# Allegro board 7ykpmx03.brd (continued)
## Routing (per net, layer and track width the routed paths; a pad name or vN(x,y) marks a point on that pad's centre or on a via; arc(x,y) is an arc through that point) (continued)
SMB_RST_N: length 68.9
  TOP w0.102: P_OCP.A9 90.06,91.8 89.53,92.33 v1(89.53,92.84)
  BOTTOM w0.102: v1(89.53,92.84) 89.53,91.57 89.84,91.26 89.84,89.61 89.41,89.18 89.41,87.63 88.87,87.1 83.44,87.1 78.05,81.71 66.12,81.71 62.99,84.84 50.16,84.84 47.24,81.91 39.78,81.91 36.88,84.81 36.88,85.37 35.76,86.49 TP21.TEST
SMB_SDA: length 64.8
  TOP w0.102: v1(89.41,89.92) 89.46,89.97 P_OCP.A8
  BOTTOM w0.102: v1(89.41,89.92) 88.39,90.93 82.8,90.93 81.98,90.11 81.98,87.34 80.85,86.21 80.85,85.14 77.93,82.22 66.5,82.22 63.25,85.47 50.04,85.47 46.93,82.36 39.96,82.36 38.07,84.25 38.07,85.5 TP20.TEST
V_1P65: length 1.1
  TOP w0.254: R35.2 112.81,250.96 ; R35.2 112.16,250.96 ; R35.2 112.48,250.63
  TOP w0.381: v1(117.31,254.38) 117.22,254.38
  vias: v1(118.2,254.38) v1(119.09,254.38) v1(119.98,254.38)
V_1P65_NEG: length 82.3
  TOP w0.254: R45.2 104.99,260.41
  TOP w0.508: 104.99,260.41 104.99,261.33 106.55,262.89 123.83,262.89 127,259.71 127,240.03 133.35,233.68 156.84,233.68 158.75,235.59 v1(159.51,235.59) ; R99.2 165.28,238.84 v1(164.85,239.27)
  vias: v1(164.47,241.68) v1(165.23,241.68)
V_3P3: length 126
  TOP w0.203: U19.5 67.42,221.87 67.67,222.12 v1(67.82,222.12) ; U8.9 C16.1
  TOP w0.254: U17.1 61.91,243.14 62.1,242.95 62.1,242.32 C130.1 v1(61.51,242.32) ; U5.5 29.96,239.66 C9.2 29.98,239.26 v1(30.23,239.01) ; U14.5 31.69,250.26 31.62,250.19 C59.2 31.24,249.81 v1(30.99,249.56) ; v1(24.26,222.38) R26.1 ; C147.1 64.77,223.14 v1(65.02,222.89) ; L10.1 v1(74.04,221.74) ; R191.2 v1(56.88,235.59) ; R36.2 v1(110.45,250.32) ; v1(30.23,234.19) 29.98,234.44 C13.2 29.96,234.84 U7.5 ; R43.2 v1(59.14,241.17) ; C16.1 105.02,240.01 v1(104.79,239.78) ; v1(30.23,231.01) 29.98,231.26 C7.2 29.96,231.66 U4.5 ; U2.5 29.96,228.49 C8.2 29.98,228.09 v1(30.23,227.84) ; U16.5 40.96,250.51 40.89,250.44 C129.2 40.51,250.06 v1(40.26,249.81) ; v1(13.73,217.68) 13.97,217.91 C5.1 14.48,218.31 ; R186.2 v1(61.48,239.52) ; v1(22.99,231.65) 23.24,231.4 C12.2 23.64,231.01 23.94,230.72 U6.5 ; R192.2 v1(50.94,235.59) ; U1.5 23.94,237.07 23.64,237.36 C6.2 23.24,237.75 v1(22.99,238) ; R187.2 v1(54.61,236.99) ; R211.2 v1(60.06,218.69) ; L7.1 63.88,222.5 v1(63.75,222.63) ; U21.5 53.48,248.14 C153.2 v1(54.06,248.16) ; R206.2 v1(72.56,225.09) ; 64.64,229.29 v1(63.94,229.29) ; R205.2 v1(69.63,229.29) ; R207.2 v1(68.26,225.09) ; R44.2 v1(59.14,241.94) ; U20.14 78.27,211.5 C152.1 v1(78.28,210.92) ; R38.2 v1(108.46,250.16) ; L8.1 v1(64.01,214.17) ; R203.2 v1(55.24,246.88) ; R17.1 v1(145.8,89.92) ; R39.2 v1(105.44,250.16) ; C131.1 v1(61.33,241.05)
  TOP w0.381: v1(36.07,87.5) 35.64,87.93 R13.1 ; R28.2 v1(20.68,239.78) ; U3.8 14.48,218.31 ; R5.1 33.6,87.93 v1(34.04,87.5) ; R1.2 v1(115.7,95.25) ; P_OCP.B11 v1(91.26,84.71) ; R20.2 v1(24.61,226.7) ; R30.2 v1(27.05,220.98) ; v1(38.1,87.5) 37.67,87.93 R12.1
  TOP w0.508: R185.2 v1(48.01,251.46) ; U11.4 24.19,245.8 v1(23.49,245.11) ; U12.4 28.76,252.04 v1(28.83,251.97) ; R10.2 v1(141.35,89.92) ; R86.2 v1(86.73,220.79) ; U13.4 v1(31.24,246.31) ; R95.1 v1(167.64,230.51) ; R9.2 v1(34.92,97.03) ; R89.2 v1(95.62,220.79) ; R88.2 v1(86.73,208.73) ; R97.1 v1(152.4,230.51) ; R87.2 v1(95.62,208.73) ; v1(40.51,246.56) U15.4
  VCC w0.254: SW_OE2.6 82.14,205.95 ; SW_OE2.6 82.14,204.78 ; SW_OE2.6 80.96,205.95 ; SW_OE2.6 80.96,204.78 ; 89.85,209.95 SW_OE1.4 ; SW_OE1.4 89.85,208.78 ; SW_OE1.4 91.03,209.95 ; SW_OE1.4 91.03,208.78 ; P_ATX.12 194.09,256.92 ; P_ATX.12 194.09,255.31 ; P_ATX.12 192.47,255.31 ; P_ATX.12 192.47,256.92 ; 80.96,208.78 SW_OE2.4 ; SW_OE2.4 82.14,209.95 ; SW_OE2.4 80.96,209.95 ; SW_OE2.4 82.14,208.78 ; 89.85,221.48 SW_OE3.4 ; SW_OE3.4 91.03,222.65 ; SW_OE3.4 91.03,221.48 ; SW_OE3.4 89.85,222.65 ; SW_OE3.6 91.03,218.65 ; SW_OE3.6 89.85,217.48 ; SW_OE3.6 91.03,217.48 ; SW_OE3.6 89.85,218.65 ; P_ATX.2 152.08,256.92 ; P_ATX.2 150.47,255.31 ; P_ATX.2 152.08,255.31 ; P_ATX.2 150.47,256.92 ; SW_OE0.6 82.14,217.48 ; SW_OE0.6 80.96,218.65 ; SW_OE0.6 82.14,218.65 ; SW_OE0.6 80.96,217.48 ; SW_OE1.6 91.03,204.78 ; SW_OE1.6 91.03,205.95 ; SW_OE1.6 89.85,204.78 ; SW_OE1.6 89.85,205.95 ; 71.37,231.73 P7.1 69.9,231.73 ; 146.27,256.92 P_ATX.1 ; P_ATX.1 147.89,256.92 ; P_ATX.1 146.27,255.31 ; P_ATX.1 147.89,255.31 ; 146.27,251.42 P_ATX.13 ; P_ATX.13 147.89,251.42 ; P_ATX.13 147.89,249.81 ; P_ATX.13 146.27,249.81 ; P6.1 58.39,231.68 ; P6.1 58.39,233.14 ; P6.1 56.92,231.68 ; P6.1 56.92,233.14 ; 47.57,224.99 SW2.1 ; SW2.1 48.95,224.99 ; SW2.1 47.57,226.36 ; SW2.1 48.95,226.36 ; 80.96,221.48 SW_OE0.4 ; SW_OE0.4 82.14,222.65 ; SW_OE0.4 80.96,222.65 ; SW_OE0.4 82.14,221.48
  BOTTOM w0.254: L9.1 68.65,214.43 v1(68.71,214.38) ; C146.1 67.44,221.74 v1(67.82,222.12)
  BOTTOM w0.406: v1(112.52,94.49) 112.47,94.54 R3.2
  vias: v1(12.07,220.47) v1(12.07,219.33) v1(17.02,175.39) v1(17.02,173.61) v1(17.02,172.09) v1(17.02,170.43) v1(17.53,200.15) v1(17.53,198.37) v1(17.53,196.85) v1(17.53,195.2) v1(17.78,110.36) v1(17.78,108.58) v1(17.78,107.06) v1(17.78,105.41) v1(17.91,144.15) v1(17.91,142.37) v1(17.91,140.84) v1(17.91,139.19) v1(21.08,87.88) v1(21.08,86.11) v1(21.08,84.58) v1(21.08,82.93) v1(22.86,87.88) v1(22.86,86.11) v1(22.86,84.58) v1(22.86,82.93) v1(24.64,87.88) v1(24.64,86.11) v1(24.64,84.58) v1(24.64,82.93) v1(25.4,209.3) v1(25.4,207.77) v1(25.4,206.12) v1(27.43,209.3) v1(27.43,207.77) v1(27.43,206.12) v1(29.34,209.3) v1(29.34,207.77) v1(29.34,206.12) v1(31.37,209.3) v1(31.37,207.77) v1(31.37,206.25) v1(32.26,236.6) v1(32.26,235.71) v1(32.26,231.01) v1(32.26,230.12) v1(33.15,234.7) v1(33.15,233.81) v1(33.15,232.92) v1(33.15,232.03) v1(87.12,83.69) v1(87.88,83.69) v1(91.19,83.82) v1(91.82,84.2) v1(137.03,254.38) v1(137.03,253.49) v1(137.03,252.6) v1(137.03,251.71) v1(137.92,256.29) v1(137.92,255.4) v1(137.92,250.7) v1(137.92,249.81)
V_5V: length 58.1
  TOP w0.254: P_ATX.4 160.48,255.31 ; P_ATX.4 158.87,256.92 ; P_ATX.4 160.48,256.92 ; P_ATX.4 158.87,255.31 ; P_ATX.6 168.89,256.92 ; P_ATX.6 167.27,256.92 ; P_ATX.6 168.89,255.31 ; P_ATX.6 167.27,255.31 ; 179.87,249.81 P_ATX.21 ; P_ATX.21 179.87,251.42 ; P_ATX.21 181.48,251.42 ; P_ATX.21 181.48,249.81 ; 188.27,249.81 P_ATX.23 ; P_ATX.23 188.27,251.42 ; P_ATX.23 189.88,251.42 ; P_ATX.23 189.88,249.81 ; 184.07,251.42 P_ATX.22 ; P_ATX.22 185.69,251.42 ; P_ATX.22 185.69,249.81 ; P_ATX.22 184.07,249.81
  TOP w0.508: 120.36,256.83 C36.2 120.79,258.88 v1(121.5,259.59)
  VCC w0.254: P_ATX.21 181.48,251.42 ; P_ATX.21 181.48,249.81 ; P_ATX.21 179.87,249.81 ; P_ATX.21 179.87,251.42 ; P_ATX.4 160.48,256.92 ; P_ATX.4 158.87,255.31 ; P_ATX.4 160.48,255.31 ; P_ATX.4 158.87,256.92 ; P_ATX.6 168.89,256.92 ; P_ATX.6 167.27,256.92 ; P_ATX.6 168.89,255.31 ; P_ATX.6 167.27,255.31 ; P_ATX.22 185.69,249.81 ; P_ATX.22 184.07,251.42 ; P_ATX.22 185.69,251.42 ; P_ATX.22 184.07,249.81 ; 188.27,249.81 P_ATX.23 ; P_ATX.23 189.88,249.81 ; P_ATX.23 189.88,251.42 ; P_ATX.23 188.27,251.42
  BOTTOM w0.254: P_ATX.4 160.48,255.31 ; P_ATX.4 158.87,255.31 ; P_ATX.4 160.48,256.92 ; P_ATX.4 158.87,256.92 ; 167.27,255.31 P_ATX.6 ; P_ATX.6 168.89,256.92 ; P_ATX.6 168.89,255.31 ; P_ATX.6 167.27,256.92
V_5VSTBY: length 37.2
  TOP w0.508: R98.1 v1(160.02,230.51)
  BOTTOM w0.381: v1(160.02,230.51) 161.93,232.41 165.74,232.41 178.5,245.18 178.5,253.94 P_ATX.9
V_12V: length 47
  TOP w0.254: 188.27,255.31 P_ATX.11 ; P_ATX.11 188.27,256.92 ; P_ATX.11 189.88,255.31 ; P_ATX.11 189.88,256.92 ; C53.1 195.8,239.81 ; C53.1 194.09,241.52 ; C53.1 195.8,241.52 ; C53.1 194.09,239.81 ; 184.07,256.92 P_ATX.10 ; P_ATX.10 184.07,255.31 ; P_ATX.10 185.69,256.92 ; P_ATX.10 185.69,255.31
  TOP w0.356: v1(85.72,87.88) 85.72,87.5 85.86,87.37 P_OCP.B2 ; v1(87.25,87.88) 87.06,87.7 P_OCP.B4 ; v1(84.96,87.88) 84.96,87.5 85.26,87.2 P_OCP.B1 ; P_OCP.B3 v1(86.46,87.88) ; P_OCP.B5 87.66,87.41 88.01,87.76 v1(88.01,87.88) ; v1(88.77,87.88) 88.77,87.63 88.26,87.12 P_OCP.B6
  TOP w0.508: v1(179.2,230.51) R101.1 ; C48.1 v1(181.74,228.6)
  VCC w0.254: 194.29,240.01 C53.1 ; C53.1 194.29,241.32 ; C53.1 195.6,240.01 ; C53.1 195.6,241.32 ; P_ATX.11 189.88,255.31 ; P_ATX.11 188.27,256.92 ; P_ATX.11 189.88,256.92 ; P_ATX.11 188.27,255.31 ; 184.07,256.92 P_ATX.10 ; P_ATX.10 185.69,256.92 ; P_ATX.10 185.69,255.31 ; P_ATX.10 184.07,255.31
  BOTTOM w0.254: 184.07,255.31 P_ATX.10 ; P_ATX.10 184.07,256.92 ; P_ATX.10 185.69,256.92 ; P_ATX.10 185.69,255.31 ; 188.27,255.31 P_ATX.11 ; P_ATX.11 188.27,256.92 ; P_ATX.11 189.88,256.92 ; P_ATX.11 189.88,255.31
  vias: v1(5.84,225.43) v1(5.84,223.52) v1(5.84,221.62) v1(5.84,219.71) v1(5.84,200.28) v1(5.84,198.37) v1(5.84,196.47) v1(5.84,194.56) v1(6.22,175.64) v1(6.22,173.74) v1(6.22,171.83) v1(6.22,169.93) v1(6.22,144.53) v1(6.22,142.62) v1(6.22,140.72) v1(6.22,138.81) v1(6.48,110.49) v1(6.48,108.58) v1(6.48,106.68) v1(6.48,104.77) v1(6.6,259.46) v1(6.6,257.56) v1(6.6,255.65) v1(6.6,253.75) v1(8.89,74.93) v1(8.89,73.02) v1(11.3,74.93) v1(11.3,73.02) v1(13.84,74.93) v1(13.84,73.02) v1(16.38,74.93) v1(16.38,73.02) v1(28.96,272.03) v1(30.86,272.03) v1(32.77,272.03) v1(34.67,272.03) v1(35.56,74.93) v1(35.56,73.02) v1(37.97,74.93) v1(37.97,73.02) v1(37.97,71.12) v1(37.97,69.22) v1(40.51,74.93) v1(40.51,73.02) v1(40.7,87.12) v1(40.7,86.23) v1(40.7,85.34) v1(40.7,84.45) v1(40.64,71.12) v1(40.64,69.22) v1(41.44,87.12) v1(41.44,86.23) v1(41.44,85.34) v1(41.44,84.45) v1(43.05,74.93) v1(43.05,73.02) v1(43.18,71.12) v1(62.74,271.78) v1(64.64,271.78) v1(66.55,271.78) v1(68.45,271.78) v1(91.95,271.65) v1(93.85,271.65) v1(95.76,271.65) v1(97.66,271.65) v1(124.97,271.78) v1(126.87,271.78) v1(128.78,271.78) v1(130.68,271.78) v1(161.67,271.53) v1(163.58,271.53) v1(165.48,271.53) v1(167.39,271.53) v1(180.34,263.52) v1(180.34,261.62) v1(182.88,263.52) v1(182.88,261.62) v1(185.42,263.52) v1(185.42,261.62) v1(187.96,263.52) v1(187.96,261.62) v1(190.5,263.52) v1(190.5,261.62) v1(193.04,263.52) v1(193.04,261.62) v1(195.45,247.02) v1(195.45,246.13) v1(195.45,245.24) v1(195.58,263.52) v1(195.58,261.62) v1(196.34,247.02) v1(196.34,246.13) v1(196.34,245.24)
V_12V_NEG: length 8.2
  TOP w0.254: 150.47,249.81 P_ATX.14 ; P_ATX.14 152.08,249.81 ; P_ATX.14 150.47,251.42 ; P_ATX.14 152.08,251.42 ; C56.2 149.83,241.32 ; C56.2 149.83,240.01 ; C56.2 148.52,241.32 ; C56.2 148.52,240.01
WAKE_N: length 48.1
  TOP w0.102: P_OCP.OCP_A3 74.27,92.61 v1(74.17,92.71)
  BOTTOM w0.102: TP4.TEST 33.02,100.08 56.52,100.08 60.2,96.39 71.25,96.39 74.17,93.47 v1(74.17,92.71)
Z_42.5_TOP: length 152.4
  TOP w0.152: Z_42.5_TOP_END.2 102.46,287.15 102.08,286.77 101.31,286.77 101.09,286.99 101.09,288.92 100.79,289.23 100.35,289.23 100.05,288.92 100.05,285.37 99.74,285.06 99.31,285.06 99,285.37 99,288.92 98.7,289.23 98.26,289.23 97.96,288.92 97.96,285.37 97.65,285.06 97.22,285.06 96.92,285.37 96.92,288.92 96.61,289.23 96.18,289.23 95.87,288.92 95.87,285.37 95.57,285.06 95.13,285.06 94.83,285.37 94.83,288.92 94.52,289.23 94.09,289.23 93.78,288.92 93.78,285.37 93.48,285.06 93.05,285.06 92.74,285.37 92.74,288.92 92.43,289.23 92,289.23 91.7,288.92 91.7,285.37 91.39,285.06 90.96,285.06 90.65,285.37 90.65,288.92 90.35,289.23 89.91,289.23 89.61,288.92 89.61,285.37 89.3,285.06 88.87,285.06 88.56,285.37 88.56,288.92 88.26,289.23 87.83,289.23 87.52,288.92 87.52,286.97 87.37,286.81 86.82,286.81 86.49,287.15 Z_42.5_TOP.2
Z_50_BOT: length 152.4
  BOTTOM w0.102: Z_50_BOT_END.2 224.59,313.44 224.46,313.57 224.46,315.3 224.16,315.59 223.75,315.59 223.46,315.3 223.46,311.57 223.17,311.28 222.76,311.28 222.47,311.57 222.47,315.3 222.18,315.59 221.77,315.59 221.48,315.3 221.48,311.57 221.19,311.28 220.77,311.28 220.48,311.57 220.48,315.3 220.19,315.59 219.78,315.59 219.49,315.3 219.49,311.57 219.2,311.28 218.79,311.28 218.5,311.57 218.5,315.3 218.21,315.59 217.79,315.59 217.5,315.3 217.5,311.57 217.21,311.28 216.8,311.28 216.51,311.57 216.51,315.3 216.22,315.59 215.81,315.59 215.52,315.3 215.52,311.57 215.23,311.28 214.81,311.28 214.52,311.57 214.52,315.3 214.23,315.59 213.82,315.59 213.53,315.3 213.53,311.57 213.24,311.28 212.83,311.28 212.54,311.57 212.54,315.3 212.25,315.59 211.84,315.59 211.54,315.3 211.54,311.57 211.25,311.28 210.84,311.28 210.55,311.57 210.55,315.3 210.26,315.59 209.85,315.59 209.56,315.3 209.56,311.57 209.27,311.28 208.86,311.28 208.57,311.57 208.57,315.3 208.27,315.59 207.86,315.59 207.57,315.3 207.57,311.57 207.28,311.28 206.87,311.28 206.58,311.57 206.58,315.3 206.29,315.59 205.88,315.59 205.59,315.3 205.59,311.57 205.29,311.28 204.88,311.28 204.59,311.57 204.59,315.3 204.3,315.59 203.89,315.59 203.6,315.3 203.6,311.57 203.31,311.28 202.9,311.28 202.61,311.57 202.61,315.3 202.32,315.59 201.9,315.59 201.61,315.3 201.61,311.57 201.32,311.28 200.91,311.28 200.62,311.57 200.62,315.3 200.33,315.59 199.92,315.59 199.63,315.3 199.63,311.57 199.34,311.28 198.92,311.28 198.63,311.57 198.63,315.3 198.34,315.59 197.93,315.59 197.64,315.3 197.64,311.57 197.35,311.28 196.94,311.28 196.65,311.57 196.65,312.5 195.71,313.44 Z_50_BOT.2
Z_50_TOP: length 152.4
  TOP w0.102: Z_50_TOP.2 194.67,296.16 195.19,295.63 195.19,294.74 195.3,294.64 196.09,294.64 196.19,294.74 196.19,297.98 196.48,298.27 196.89,298.27 197.18,297.98 197.18,294.35 197.47,294.06 197.88,294.06 198.17,294.35 198.17,297.98 198.47,298.27 198.88,298.27 199.17,297.98 199.17,294.35 199.46,294.06 199.87,294.06 200.16,294.35 200.16,297.98 200.45,298.27 200.86,298.27 201.15,297.98 201.15,294.35 201.44,294.06 201.86,294.06 202.15,294.35 202.15,297.98 202.44,298.27 202.85,298.27 203.14,297.98 203.14,294.35 203.43,294.06 203.84,294.06 204.13,294.35 204.13,297.98 204.42,298.27 204.84,298.27 205.13,297.98 205.13,294.35 205.42,294.06 205.83,294.06 206.12,294.35 206.12,297.98 206.41,298.27 206.82,298.27 207.11,297.98 207.11,294.35 207.4,294.06 207.81,294.06 208.11,294.35 208.11,297.98 208.4,298.27 208.81,298.27 209.1,297.98 209.1,294.35 209.39,294.06 209.8,294.06 210.09,294.35 210.09,297.98 210.38,298.27 210.79,298.27 211.08,297.98 211.08,294.35 211.38,294.06 211.79,294.06 212.08,294.35 212.08,297.98 212.37,298.27 212.78,298.27 213.07,297.98 213.07,294.35 213.36,294.06 213.77,294.06 214.06,294.35 214.06,297.98 214.36,298.27 214.77,298.27 215.06,297.98 215.06,294.35 215.35,294.06 215.76,294.06 216.05,294.35 216.05,297.98 216.34,298.27 216.75,298.27 217.04,297.98 217.04,294.35 217.33,294.06 217.75,294.06 218.04,294.35 218.04,297.98 218.33,298.27 218.74,298.27 219.03,297.98 219.03,294.35 219.32,294.06 219.73,294.06 220.02,294.35 220.02,297.98 220.31,298.27 220.73,298.27 221.02,297.98 221.02,294.35 221.31,294.06 221.72,294.06 222.01,294.35 222.01,297.98 222.3,298.27 222.71,298.27 223,297.98 223,294.35 223.29,294.06 223.7,294.06 224,294.35 224,295.47 224.69,296.16 Z_50_TOP_END.2
Z_85D_BOT_DN: length 152.4
  BOTTOM w0.127: 13.34,292.73 13.34,293.73 13.46,293.85 14.88,293.85 15.35,294.32 15.35,294.76 15.53,295.79 15.35,296.83 15.35,297.29 16.26,298.2 17.16,298.2 18.41,297.98 20.91,298.42 23.41,297.98 25.91,298.42 28.41,297.98 30.91,298.42 33.41,297.98 35.92,298.42 38.42,297.98 40.92,298.42 43.42,297.98 45.92,298.42 48.42,297.98 50.92,298.42 53.43,297.98 55.91,298.41 57.15,298.2 57.66,298.2 58.29,297.56 58.29,293.5 58.09,293.29 57.84,293.29 57.2,293.18 55.3,293.51 52.8,293.07 50.3,293.51 47.8,293.07 45.3,293.51 42.8,293.07 40.3,293.51 37.79,293.07 35.29,293.51 32.79,293.07 30.29,293.51 27.79,293.07 25.29,293.51 22.79,293.07 20.28,293.51 17.78,293.07 17.12,293.19 16.47,292.91 16.21,292.51 16.21,289.56 16.79,288.68 17.12,288.53 18.12,288.71 20.62,288.27 23.12,288.71 25.62,288.27 28.12,288.71 30.63,288.27 33.13,288.71 35.63,288.27 38.13,288.71 40.63,288.27 43.13,288.71 45.63,288.27 48.14,288.71 50.64,288.27 53.14,288.71 55.64,288.27 57.97,288.68 59.03,288.49 59.56,288.49 60.64,289.57 60.64,290.54 60.42,291.79 60.64,293.04 60.64,293.43 61.06,293.85 61.94,293.85 Z_85D_BOT_END.3
Z_85D_BOT_DP: length 152.4
  BOTTOM w0.127: 13.34,295.27 13.34,294.28 13.46,294.16 14.76,294.16 15.05,294.45 15.05,294.79 15.22,295.79 15.05,296.8 15.05,297.42 16.13,298.5 17.18,298.5 18.41,298.28 20.91,298.73 23.41,298.28 25.91,298.73 28.41,298.28 30.91,298.73 33.41,298.28 35.92,298.73 38.42,298.28 40.92,298.73 43.42,298.28 45.92,298.73 48.42,298.28 50.92,298.73 53.43,298.28 55.91,298.72 57.18,298.5 57.78,298.5 58.6,297.69 58.6,293.37 58.22,292.99 57.86,292.99 57.19,292.87 55.3,293.2 52.8,292.76 50.3,293.2 47.8,292.76 45.3,293.2 42.8,292.76 40.3,293.2 37.79,292.76 35.29,293.2 32.79,292.76 30.29,293.2 27.79,292.76 25.29,293.2 22.79,292.76 20.28,293.2 17.78,292.76 17.15,292.87 16.68,292.67 16.51,292.41 16.51,289.65 16.99,288.92 17.15,288.85 18.12,289.02 20.62,288.58 23.12,289.02 25.62,288.58 28.12,289.02 30.63,288.58 33.13,289.02 35.63,288.58 38.13,289.02 40.63,288.58 43.13,289.02 45.63,288.58 48.14,289.02 50.64,288.58 53.14,289.02 55.64,288.58 57.97,288.99 59.05,288.8 59.44,288.8 60.34,289.7 60.34,290.51 60.11,291.79 60.34,293.06 60.34,293.56 60.94,294.16 61.94,294.16 Z_85D_BOT_END.2
Z_85D_TOP_DN: length 152.4
  TOP w0.127: Z_85D_TOP_END.3 61.94,312.9 59.97,312.9 59.11,312.04 59.11,311.8 59.33,310.52 59.11,309.25 59.11,308.36 56.13,305.38 55.24,305.38 54.94,305.33 53.38,305.6 50.88,305.16 48.38,305.6 47.13,305.38 46.74,305.38 46.3,305.82 46.3,307.97 46.61,308.28 47.34,308.28 47.84,308.37 49.56,308.06 52.07,308.51 53.34,308.28 53.85,308.28 54.23,308.66 54.23,310.08 53.85,310.46 53.32,310.46 52.07,310.68 49.56,310.24 47.06,310.68 44.56,310.24 42.06,310.68 39.56,310.24 37.06,310.68 34.56,310.24 32.05,310.68 29.55,310.24 27.05,310.68 24.55,310.24 22.06,310.68 20.83,310.46 19.94,310.46 19.51,310.9 19.51,313.56 19.94,313.99 20.82,313.99 22.1,314.22 24.6,313.78 27.1,314.22 29.6,313.78 32.1,314.22 34.6,313.78 37.1,314.22 39.61,313.78 42.11,314.22 44.61,313.78 47.11,314.22 49.61,313.78 52.11,314.22 53.39,313.99 53.85,313.99 54.23,314.38 54.23,315.54 53.85,315.93 53.35,315.93 52.1,316.15 49.6,315.7 47.09,316.15 44.59,315.7 42.09,316.15 39.59,315.7 37.09,316.15 34.59,315.7 32.09,316.15 29.58,315.7 27.08,316.15 24.58,315.7 22.08,316.15 20.45,315.86 20.07,315.93 19.18,315.93 16.15,312.9 13.46,312.9 13.34,312.78
  TOP w0.152: 13.34,311.78 13.34,312.78
Z_85D_TOP_DP: length 152.4
  TOP w0.127: Z_85D_TOP_END.2 61.94,313.21 59.84,313.21 58.8,312.17 58.8,311.77 59.02,310.52 58.8,309.27 58.8,308.48 56.01,305.69 55.22,305.69 54.94,305.64 53.38,305.91 50.88,305.47 48.38,305.91 47.1,305.69 46.86,305.69 46.61,305.94 46.61,307.85 46.74,307.97 47.37,307.97 47.84,308.06 49.56,307.75 52.07,308.2 53.32,307.97 53.97,307.97 54.53,308.53 54.53,310.21 53.97,310.77 53.34,310.77 52.07,310.99 49.56,310.55 47.06,310.99 44.56,310.55 42.06,310.99 39.56,310.55 37.06,310.99 34.56,310.55 32.05,310.99 29.55,310.55 27.05,310.99 24.55,310.55 22.06,310.99 20.8,310.77 20.07,310.77 19.81,311.02 19.81,313.44 20.07,313.69 20.85,313.69 22.1,313.91 24.6,313.47 27.1,313.91 29.6,313.47 32.1,313.91 34.6,313.47 37.1,313.91 39.61,313.47 42.11,313.91 44.61,313.47 47.11,313.91 49.61,313.47 52.11,313.91 53.36,313.69 53.97,313.69 54.53,314.25 54.53,315.67 53.97,316.23 53.37,316.23 52.1,316.46 49.6,316.01 47.09,316.46 44.59,316.01 42.09,316.46 39.59,316.01 37.09,316.46 34.59,316.01 32.09,316.46 29.58,316.01 27.08,316.46 24.58,316.01 22.08,316.46 20.45,316.17 20.09,316.23 19.05,316.23 16.03,313.21 13.46,313.21 13.34,313.33
  TOP w0.152: 13.34,314.32 13.34,313.33
N16775589: length 25.8
  TOP w0.102: U5.2 27.56,239.01 27.69,239.14 27.69,239.52 27.54,239.66 U5.1 25.41,239.66 25.02,239.27 25.02,235.2 24.75,234.93 U1.4 23.94,234.51 23.42,233.99 R21.2 23.42,233.12 23.62,232.92 23.62,232.41 ; 25.26,231.66 25.02,231.42 25.02,228.98 25.51,228.49 U2.1 ; 25.26,231.66 24.77,232.16 23.88,232.16 23.62,232.41 ; 25.26,231.66 U4.1 ; 23.62,232.41 23.37,232.16 22.1,232.16 20.95,231.01 20.95,230.12 21.19,229.89 U6.1
N16775601: length 23
  TOP w0.102: v1(22.99,232.66) 22.56,233.1 R21.1
  BOTTOM w0.102: v1(22.99,232.66) 24.13,231.52 24.13,230.38 29.08,225.43 33.4,225.43 35.81,223.01 35.81,222 P2.1
N16775717: length 12.3
  TOP w0.102: v1(24.64,227.58) 24.56,227.58 23.94,228.21 U6.4 ; U1.2 v1(20.83,235.59)
  BOTTOM w0.102: v1(24.64,227.58) 20.57,231.65 20.57,235.33 v1(20.83,235.59)
N16776117: length 13.7
  TOP w0.102: U2.2 27.53,227.84 27.69,228 27.69,230.25 27.8,230.36 U4.4 30.46,230.36 30.99,230.89 30.99,232.54 29.34,234.19 28.19,234.19 27.54,234.84 U7.1
N16776223: length 4.2
  TOP w0.102: U7.4 27.85,233.54 27.69,233.38 27.69,231.17 27.53,231.01 U4.2
N16776317: length 7.9
  TOP w0.102: U7.2 25.77,234.19 25.4,234.56 25.4,236.09 25.91,236.6 C14.1 26.85,237.41 27.05,237.62 27.43,237.62 27.69,237.87 27.69,238.2 27.85,238.36 U5.4
N16776527: length 28.1
  TOP w0.102: R22.2 24.21,219.91 24.38,220.09 25.53,220.09 27.3,218.31 35.31,218.31 35.81,218.82 35.81,224.79 33.42,227.19 U2.4
  TOP w0.127: R22.2 R25.1
N16776623: length 18.9
  TOP w0.102: R22.1 25.53,219.58 27.05,218.06 41.15,218.06 P1.1
N16777522: length 1.2
  TOP w0.102: U8.8 105.77,240.81 105.41,241.17 R33.2
N16798679: length 6.9
  TOP w0.102: X_OSC1.1 110.83,258.95 111.09,259.21 112.48,259.21 112.86,258.83 R37.2
N16831523: length 1.3
  TOP w0.102: DS_3P3V.1 R97.2
N16831963: length 1.3
  TOP w0.102: DS_5VSTBY.1 R98.2
N16832324: length 1.7
  TOP w0.102: Q1.3 DS_RST.2
N16832328: length 1.3
  TOP w0.102: DS_RST.1 R95.2
N16833101: length 1.8
  TOP w0.102: DS_TRIG.1 R101.2
N16833103: length 3.8
  TOP w0.102: Q2.3 DS_TRIG.2 184.32,229.4 184.23,229.31 C48.2
N16884462: length 2.2
  TOP w0.102: U16.1 45.4,250.51 45.47,250.44 R118.2
N17027072: length 1.9
  TOP w0.102: U19.8 65.48,220.53 65.41,220.6 65.41,220.85 v1(65.28,220.98)
  BOTTOM w0.102: R202.2 65.58,220.68 v1(65.28,220.98)
N17042432: length 21.4
  TOP w0.102: R187.1 54.61,239.01 54.46,239.16 54.46,239.64 54.48,239.66 U18.8 ; R187.1 v1(53.91,238.56) ; R187.1 R193.2 ; SW2.2 50.8,227.2 48.13,229.87 48.13,234.82 v1(51.94,238.63)
  BOTTOM w0.102: v1(53.91,238.56) 52.02,238.56 v1(51.94,238.63)
N17054983: length 6.5
  TOP w0.102: U17.3 v1(64.56,244.24) ; R186.1 v1(63.74,239.52)
  BOTTOM w0.102: v1(64.56,244.24) 63.74,243.42 v1(63.74,239.52)
N17056716: length 3.6
  TOP w0.102: R188.1 58.24,243.38 58.04,243.59 57.28,243.59 56.9,243.21 56.9,242.7 56.41,242.21 U18.14
N17056744: length 2
  TOP w0.102: U18.16 55.24,243.4 R203.1
N17069423: length 2.9
  TOP w0.102: 58.55,213.23 R212.2
N17072145: length 5.8
  TOP w0.102: R217.1 208.64,236.96 210.03,238.35 DS2.1
N17072148: length 3
  TOP w0.102: P9.2 211.53,233.73 R217.2
N17072154: length 5.2
  TOP w0.102: DS2.2 212.78,236.8 214.12,235.46 P9.1
N17072580: length 3
  TOP w0.102: R216.2 32.97,259.66 P8.2
N17072594: length 5.2
  TOP w0.102: DS1.2 31.67,260.91 P8.1
N17073446: length 6.1
  TOP w0.102: R218.1 54.64,256.77 53.75,257.66 DS3.1
N17073448: length 3
  TOP w0.102: R218.2 58.37,259.66 P10.2
N17073464: length 5.2
  TOP w0.102: DS3.2 57.07,260.91 P10.1
N17073631: length 6.1
  TOP w0.102: DS1.1 28.35,257.66 29.24,256.77 R216.1

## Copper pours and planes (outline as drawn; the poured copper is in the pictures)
GND on TOP: 27.86,237.24 27.86,235.97 29.64,235.97 29.77,236.09 29.77,237.11 29.64,237.24
GND on TOP: 87.25,80.9 87.25,82.42 87.5,82.68 90.68,82.68 90.8,82.55 90.8,81.15 89.03,79.38 88.65,79.38 88.27,78.99 87,78.99 86.74,79.25 86.74,80.52 87.12,80.9
GND on TOP: 23.37,224.41 23.37,223.14 25.15,223.14 25.27,223.27 25.27,224.28 25.15,224.41
GND on TOP: 12.19,221.23 12.19,222.5 10.41,222.5 10.29,222.38 10.29,221.36 10.41,221.23
GND on TOP: 35.81,228.6 38.73,228.6 39.37,229.24 39.37,237.49 38.73,238.12 35.81,238.12 35.18,237.49 35.18,229.24
GND on TOP: 134.37,257.81 131.44,257.81 130.81,257.18 130.81,248.92 131.44,248.29 134.37,248.29 135,248.92 135,257.18
GND on BOTTOM: 157.35,236.6 157.35,235.08 157.23,234.95 154.81,234.95 154.69,235.08 154.69,238.63 154.94,238.89 155.58,238.89 155.83,238.63 155.83,236.98 156.08,236.73 157.23,236.73
GND on BOTTOM: 118.11,252.09 116.59,252.09 116.46,251.97 116.46,249.56 116.59,249.43 120.14,249.43 120.4,249.68 120.4,250.32 120.14,250.57 118.49,250.57 118.24,250.83 118.24,251.97
GND on BOTTOM: 118.11,256.54 116.59,256.54 116.46,256.67 116.46,259.08 116.59,259.21 120.14,259.21 120.4,258.95 120.4,258.32 120.14,258.06 118.49,258.06 118.24,257.81 118.24,256.67
GND on BOTTOM: 161.8,236.6 161.8,235.08 161.93,234.95 164.34,234.95 164.47,235.08 164.47,238.63 164.21,238.89 163.58,238.89 163.32,238.63 163.32,236.98 163.07,236.73 161.93,236.73
GND on GND: 240.67,0.63 0.63,0.63 0.63,278.51 0.89,278.76 240.28,278.76 240.67,278.38 ; 104 cut-outs
GND on VCC: 240.67,138.53 240.67,0.63 0.63,0.63 0.63,67.18 41.66,67.18 48.64,74.17 48.64,81.66 49.53,82.55 60.32,82.55 63.88,78.99 82.93,78.99 85.47,81.53 91.44,81.53 92.71,82.8 92.71,87.63 92.46,87.88 92.46,92.2 92.08,92.58 92.08,93.85 92.58,94.36 111,94.36 111.76,93.6 139.19,93.6 140.08,92.71 140.08,89.28 140.59,88.77 146.43,88.77 146.81,89.15 146.81,95.38 144.4,97.79 89.41,97.79 84.33,92.71 40.13,92.71 39.24,93.6 39.24,95.5 36.07,98.68 26.42,98.68 25.65,99.44 25.65,187.96 36.2,198.5 95.63,198.5 99.44,202.31 99.44,221.74 103.63,225.93 240.54,225.93 240.67,225.81 240.67,171.2 240.69,171.17 240.69,138.53 ; 39 cut-outs
GND on GD2: 240.67,0.63 0.63,0.63 0.63,278.51 0.89,278.76 240.28,278.76 240.67,278.38 ; 17 cut-outs
GND on GD3: 240.67,0.63 0.63,0.63 0.63,278.51 0.89,278.76 240.28,278.76 240.67,278.38 ; 17 cut-outs
GND_SIGNAL on TOP: 172.21,305.31 168.91,305.31 168.71,305.51 168.71,306.5 168.91,306.7 172.21,306.7 172.42,306.5 172.42,305.51
GND_SIGNAL on TOP: 168.91,303.02 172.21,303.02 172.42,302.82 172.42,301.83 172.21,301.62 168.91,301.62 168.71,301.83 168.71,302.82
GND_SIGNAL on BOTTOM: 135.89,323.09 138.94,323.09 139.29,323.44 139.29,329.13 138.94,329.13 138.94,326.95 138.89,326.9 138.73,326.9 138.68,326.95 138.68,328.73 138.33,328.73 138.33,326.95 138.28,326.9 138.15,326.9 138.1,326.95 138.1,328.73 137.74,328.73 137.74,326.95 137.69,326.9 137.54,326.9 137.49,326.95 137.49,329.13 137.13,329.13 137.13,326.95 137.08,326.9 136.93,326.9 136.88,326.95 136.88,328.73 136.53,328.73 136.53,326.95 136.47,326.9 136.35,326.9 136.3,326.95 136.3,328.73 135.94,328.73 135.94,323.98 135.76,323.8 135.76,323.21
GND_SIGNAL on GND: 85.78,324.53 86.11,323.72 86.91,323.39 88.41,323.39 89.22,323.72 89.55,324.53 89.55,329.01 89.93,329.39 106.26,329.39 106.64,329.01 106.64,324.4 108.65,322.39 110.66,324.4 110.66,329.01 111.04,329.39 118.97,329.39 119.35,329.01 119.35,323.95 120.91,322.39 122.47,323.95 122.47,329.01 122.85,329.39 139.17,329.39 139.55,329.01 139.55,324.15 141.31,322.39 143.07,324.15 143.07,329.01 143.45,329.39 151.38,329.39 151.75,329.01 151.75,324.53 152.09,323.72 152.89,323.39 154.39,323.39 155.19,323.72 155.52,324.53 155.52,329.01 155.9,329.39 156.55,329.39 158.01,326.86 158.01,325.16 158.51,323.96 159.72,323.46 240.66,323.46 240.66,282.4 0.63,282.4 0.63,323.46 81.58,323.46 82.79,323.96 83.28,325.16 83.28,326.86 84.75,329.39 85.4,329.39 85.78,329.01 ; 15 cut-outs
GND_SIGNAL on VCC: 85.78,324.53 86.11,323.72 86.91,323.39 88.41,323.39 89.22,323.72 89.55,324.53 89.55,329.01 89.93,329.39 106.26,329.39 106.64,329.01 106.64,324.4 108.65,322.39 110.66,324.4 110.66,329.01 111.04,329.39 118.97,329.39 119.35,329.01 119.35,323.95 120.91,322.39 122.47,323.95 122.47,329.01 122.85,329.39 139.17,329.39 139.55,329.01 139.55,324.15 141.31,322.39 143.07,324.15 143.07,329.01 143.45,329.39 151.38,329.39 151.75,329.01 151.75,324.53 152.09,323.72 152.89,323.39 154.39,323.39 155.19,323.72 155.52,324.53 155.52,329.01 155.9,329.39 156.55,329.39 158.01,326.86 158.01,325.16 158.51,323.96 159.72,323.46 240.66,323.46 240.66,282.4 0.63,282.4 0.63,323.46 81.58,323.46 82.79,323.96 83.28,325.16 83.28,326.86 84.75,329.39 85.4,329.39 85.78,329.01 ; 15 cut-outs
GND_SIGNAL on GD2: 85.78,324.53 86.11,323.72 86.91,323.39 88.41,323.39 89.22,323.72 89.55,324.53 89.55,329.01 89.93,329.39 106.26,329.39 106.64,329.01 106.64,324.4 108.65,322.39 110.66,324.4 110.66,329.01 111.04,329.39 118.97,329.39 119.35,329.01 119.35,323.95 120.91,322.39 122.47,323.95 122.47,329.01 122.85,329.39 139.17,329.39 139.55,329.01 139.55,324.15 141.31,322.39 143.07,324.15 143.07,329.01 143.45,329.39 151.38,329.39 151.75,329.01 151.75,324.53 152.09,323.72 152.89,323.39 154.39,323.39 155.19,323.72 155.52,324.53 155.52,329.01 155.9,329.39 156.55,329.39 158.01,326.86 158.01,325.16 158.51,323.96 159.72,323.46 240.66,323.46 240.66,282.4 0.63,282.4 0.63,323.46 81.58,323.46 82.79,323.96 83.28,325.16 83.28,326.86 84.75,329.39 85.4,329.39 85.78,329.01 ; 6 cut-outs
GND_SIGNAL on GD3: 85.78,324.53 86.11,323.72 86.91,323.39 88.41,323.39 89.22,323.72 89.55,324.53 89.55,329.01 89.93,329.39 106.26,329.39 106.64,329.01 106.64,324.4 108.65,322.39 110.66,324.4 110.66,329.01 111.04,329.39 118.97,329.39 119.35,329.01 119.35,323.95 120.91,322.39 122.47,323.95 122.47,329.01 122.85,329.39 139.17,329.39 139.55,329.01 139.55,324.15 141.31,322.39 143.07,324.15 143.07,329.01 143.45,329.39 151.38,329.39 151.75,329.01 151.75,324.53 152.09,323.72 152.89,323.39 154.39,323.39 155.19,323.72 155.52,324.53 155.52,329.01 155.9,329.39 156.55,329.39 158.01,326.86 158.01,325.16 158.51,323.96 159.72,323.46 240.66,323.46 240.66,282.4 0.63,282.4 0.63,323.46 81.58,323.46 82.79,323.96 83.28,325.16 83.28,326.86 84.75,329.39 85.4,329.39 85.78,329.01 ; 6 cut-outs
VCC_OSC1 on TOP: 112.1,254.38 110.07,254.38 109.94,254.25 109.94,251.46 110.07,251.33 113.12,251.33 113.13,251.34 113.42,251.34 113.66,251.59 113.66,254.89 113.54,255.02 112.36,255.02 112.23,254.89 112.23,254.51
555_DISCHARGE on TOP: 14.61,219.28 16.38,219.28 16.61,219.51 16.61,219.71 16.43,219.89 14.63,219.89 14.53,219.99 14.53,220.45 14.63,220.55 16.38,220.55 16.59,220.75 16.59,220.98 16.41,221.16 14.63,221.16 14.48,221.31 14.48,222.38 14.35,222.5 13.05,222.5 12.9,222.35 12.9,221.49 13.51,220.88 13.51,220.04 13.44,219.96 13.44,219.05 13.49,219 14.33,219
V_1P65 on TOP: 119.47,255.52 119.47,257.68 119.21,257.94 117.69,257.94 117.44,257.68 117.44,255.52 117.31,255.4 115.82,255.4 115.19,256.03 115.19,258.95 115.11,259.03 114.12,259.03 114.05,258.95 114.05,251.59 113.54,251.08 112.14,251.08 112.01,250.95 112.01,249.81 112.39,249.43 115.82,249.43 115.95,249.56 115.95,252.86 116.2,253.11 116.84,253.11 117.09,252.86 117.09,250.95 117.22,250.83 118.41,250.83 118.54,250.7 118.54,249.58 118.62,249.5 119.48,249.5 119.6,249.62 119.6,253.37 120.36,254.13 120.36,254.64
V_1P65 on BOTTOM: 120.4,255.91 120.14,256.16 116.59,256.16 116.46,256.03 116.46,252.73 116.59,252.6 120.14,252.6 120.4,252.86
V_1P65_NEG on TOP: 165.35,241.43 163.96,241.43 163.83,241.55 163.83,242.32 163.65,242.49 161.29,242.49 161.29,243.43 164.82,243.43 164.9,243.36 164.9,242.52 165.48,241.94 165.48,241.55
V_1P65_NEG on BOTTOM: 157.73,235.08 157.86,234.95 161.16,234.95 161.29,235.08 161.29,238.63 161.8,239.14 164.34,239.14 164.59,238.89 165.61,238.89 165.86,239.14 165.86,241.81 165.48,242.19 158.12,242.19 157.73,241.81
V_3P3 on TOP: 11.81,220.83 11.93,220.95 13.03,220.95 13.16,220.83 13.16,218.9 13.08,218.82 11.94,218.82 11.81,218.95
V_3P3 on TOP: 31.75,228.6 34.04,228.6 34.67,229.24 34.67,237.49 34.04,238.12 31.75,238.12 31.12,237.49 31.12,229.24
V_3P3 on TOP: 92.2,83.06 92.46,83.31 92.46,84.96 92.08,85.34 90.93,85.34 89.84,84.25 86.97,84.25 86.87,84.15 86.87,83.13 86.94,83.06
V_3P3 on TOP: 138.43,257.81 136.14,257.81 135.51,257.18 135.51,248.92 136.14,248.29 138.43,248.29 139.07,248.92 139.07,257.18
V_3P3 on BOTTOM: 86.87,83.87 86.87,83.31 87.27,82.91 89.03,82.91 89.09,82.97 89.09,84.01 88.9,84.2 87.76,84.2 87.5,83.95 86.94,83.95
V_3P3 on BOTTOM: 13.46,212.34 31.88,212.34 43.56,200.66 43.56,153.29 26.29,136.02 26.29,82.17 25.65,81.53 13.08,81.53 11.56,83.06 11.56,210.44
V_3P3 on VCC: outline of 92 points within 11.56,80.71 200.41,266.7 ; 54 cut-outs
V_5V on TOP: 182.25,260.35 181.61,260.99 158.75,260.99 158.12,260.35 158.12,246.38 158.75,245.75 189.87,245.75 190.5,246.38 190.5,251.71 189.48,252.73 182.88,252.73 182.25,253.37
V_5V on BOTTOM: 139.7,258.57 121.54,258.57 121.03,259.08 121.03,260.22 123.32,262.51 155.07,262.51 157.73,259.84 157.73,259.71 170.18,259.71 170.82,259.08 170.82,254 170.18,253.37 159.39,253.37 158.12,252.09 158.12,249.56 153.04,244.48 141.86,244.48 139.7,246.63
V_5V on VCC: 120.9,262.64 120.4,262.13 120.4,258.19 120.9,257.68 141.35,257.68 142.11,258.44 157.48,258.44 157.99,257.94 157.99,248.03 158.75,247.27 189.87,247.27 190.5,247.9 190.5,252.86 190.12,253.24 178.31,253.24 177.67,253.87 177.67,261.75 176.78,262.64
V_12V on TOP: 41.78,87.66 39.65,87.66 39.45,87.45 39.45,83.77 39.65,83.57 41.78,83.57 41.91,83.69 41.91,87.53
V_12V on TOP: 200.66,260.99 183.52,260.99 182.88,260.35 182.88,254 183.52,253.37 189.87,253.37 191.14,252.09 191.14,238.76 191.77,238.12 200.66,238.12 201.3,238.76 201.3,260.35
V_12V on BOTTOM: 40.46,84.23 41.61,84.23 41.73,84.35 41.73,87.27 41.61,87.4 40.59,87.4 40.34,87.15 40.34,84.35
V_12V on BOTTOM: 198.12,277.75 17.14,277.75 1.02,261.62 1.02,68.96 2.16,67.82 41.15,67.82 43.56,70.23 43.56,75.74 42.98,76.33 34.54,76.33 30.86,80.01 13.34,80.01 10.54,82.8 10.54,253.24 24.38,267.08 170.05,267.08 177.67,259.46 180.85,259.46 183.13,257.18 183.13,254 184.79,252.35 196.09,252.35 198.25,254.51 198.25,277.62
V_12V on VCC: 1.02,67.82 0.63,68.2 0.63,278.51 0.89,278.76 240.03,278.76 240.03,226.95 239.78,226.7 178.94,226.7 178.56,227.08 178.56,231.01 178.94,231.39 187.96,231.39 193.17,236.6 193.17,242.19 195.07,244.09 195.07,247.14 195.33,247.4 200.41,247.4 201.17,248.16 201.17,259.21 199.77,260.6 191.01,260.6 190.5,260.1 190.5,254.38 189.99,253.87 179.2,253.87 178.31,254.76 178.31,261.87 176.91,263.27 120.9,263.27 120.65,263.52 120.65,266.06 119.76,266.95 24.51,266.95 10.79,253.24 10.79,82.93 13.59,80.14 38.23,80.14 39.62,81.53 39.62,87.88 40,88.27 72.39,88.27 75.31,85.34 82.04,85.34 84.45,87.76 84.45,88.14 84.71,88.39 88.9,88.39 89.15,88.14 89.15,85.72 88.9,85.47 87.88,85.47 86.87,84.45 86.74,84.45 86.23,83.95 86.23,83.44 82.55,79.76 63.75,79.76 60.32,83.19 49.53,83.18 48.26,81.91 48.26,74.93 41.15,67.82 ; 1 cut-out
V_12V_NEG on TOP: 140.34,260.99 156.84,260.99 157.48,260.35 157.48,241.3 157.61,241.17 164.59,241.17 164.72,241.05 164.72,240.28 164.59,240.16 157.61,240.16 157.48,240.03 157.48,238.76 156.84,238.12 140.34,238.12 139.7,238.76 139.7,260.35

Small or netless copper shapes (teardrops, artwork), in the pictures only: 164 on TOP

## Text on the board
Ref Des/Assembly Top: X*
Ref Des/Silkscreen Top: ANODE | CATHODE | PWB 7YKPM | MADE IN _____ | UL94V-0 | REV ___ | CMTS AUTOMATION | CONNECTOR | RST Switch | PCIE | RESET AUTOMATION | EXT | OSC | CMTS Switch | ON | OFF | OCP3.0 PCIE CBB GEN 5
DIMENSION: 2X 20 | +/- 2 | ENSURE SOLDERABILITY. | 6     .005   .007       5        85 OHM   +/- 20% | .055 | EDGE BEVEL | SECTION A
DEVICE_TYPE_TOP: DEVICE
USER_PART_NUM_TOP: PART# | OCP3, SI5, TX, PCIE | THIS CONTRIBUTION IS PROVIDED WITHOUT WARRANTY OF | ANY KIND AND IS PROVIDED AS-IS, AND THE | IMPLIED, OR STATUTORY. | CONTRIBUTOR DISCLAIMS ALL WARRANTIES, INCLUDING | WITHOUT LIMITATION WARRANTIES OF NON-INFRINGEMENT, | MERCHANTABILITY AND FITNESS FOR A PARTICULAR | PURPOSE, AS WELL AS ANY WARRANTIES EXPRESS,
COMPVAL_TYPE_TOP: VALUE
TOLERANCE_TOP: TOL
User.27: FIGURE | FINISHED_SIZE | 8.0 | 8.02 | 10.0 | 12.0 | 28.0 | 31.0 | 32.0 | 38.0 | 42.9134 | 47.0 | 55.0 | 42.0 | 43.3071 | 50.0 | 118.0 | 125.0 | 96.4567x43.3071 | DRILL CHART: TOP to BOTTOM | ALL UNITS ARE IN MILS | TOLERANCE_DRILL | +3.0/-3.0 | +3.0/-7.0 | +3.0/-5.0 | +4.0/-10.0 | +3.0/-10.0 | +2.0/-2.0 | +9.8425/-9.8425 | +1.0/-2.0 | +2.0/-0.0 | PLATED | NON-PLATED | QTY | 738 | 638 | 9 | 6 | 17 | 36 | 328 | 4 | 48 | 24 | 20 | 2 | 12 | 8 | 5 | 1948 | TOTAL HOLES:
